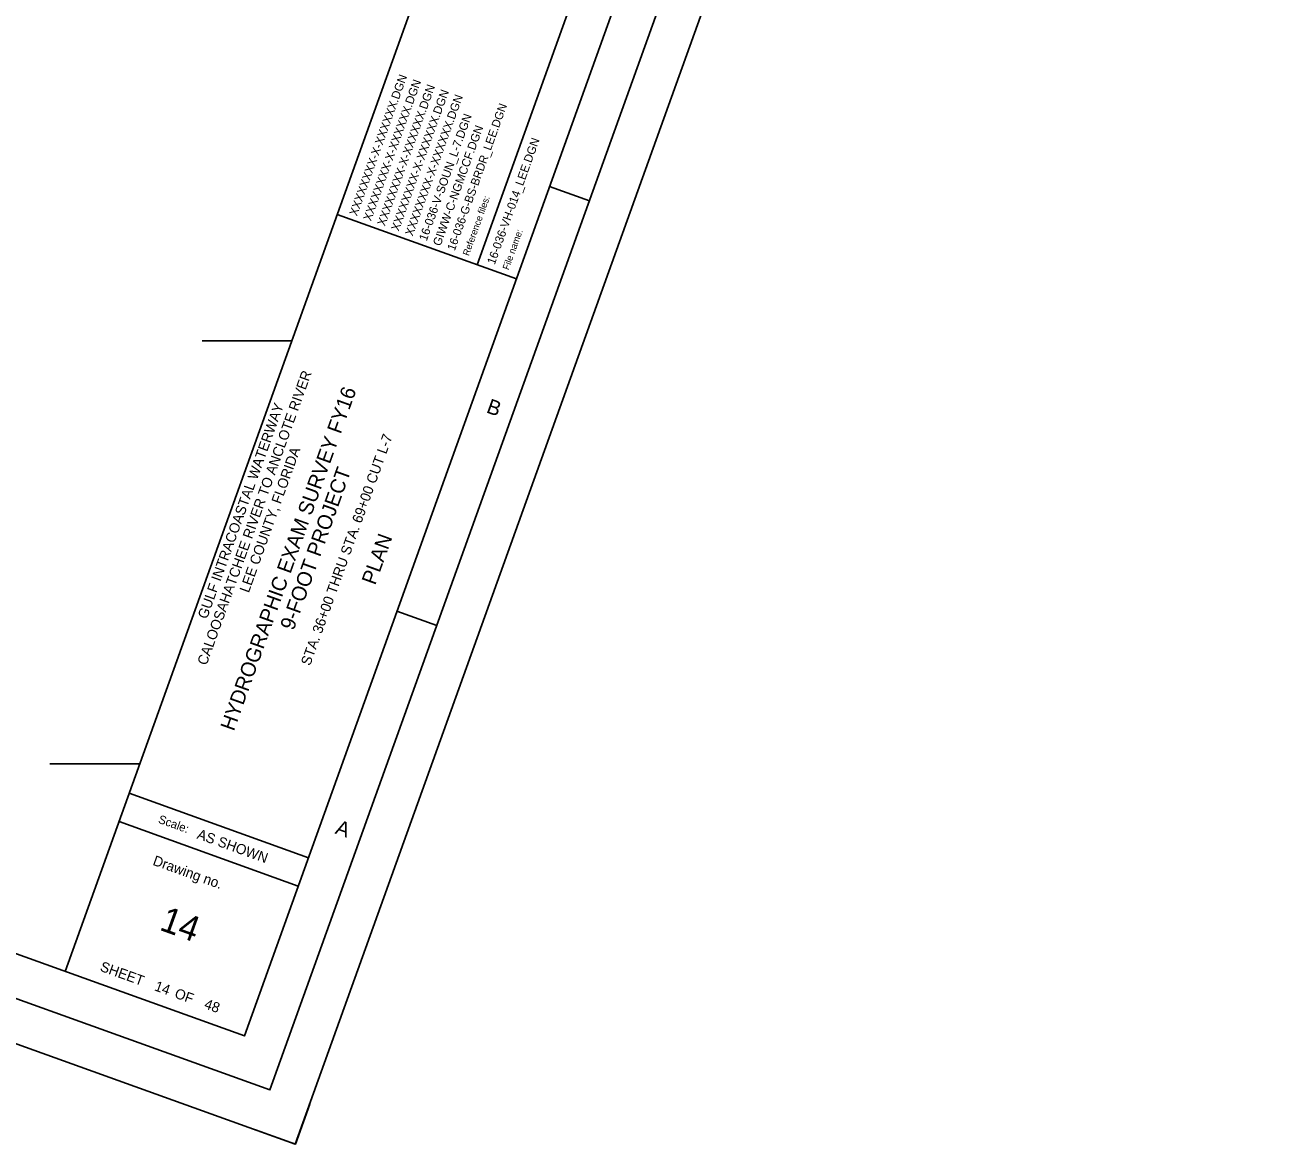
# Model space of a CAD drawing. Extents: x 609104 to 614395, y 782051 to 786739.
# Drawn here: x 612925 to 614395, y 782051 to 783373 of the extents above; entities that cross this region are included whole.
import ezdxf

# ---------------------------------------------------------------- set-up
doc = ezdxf.new("R2010")
doc.units = 0
for name, color, linetype in [('G-ANNO-NPLT', 7, 'Continuous'), ('G-ANNO-TEXT-DRWG', 7, 'Continuous'), ('G-ANNO-TEXT-PROJ', 7, 'Continuous'), ('G-ANNO-TEXT-TTLB', 7, 'Continuous'), ('G-ANNO-TTLB', 7, 'Continuous'), ('V-TOPO-COOR-STAT', 7, 'Continuous')]:
    doc.layers.add(name, color=color, linetype=linetype)

msp = doc.modelspace()

# ---------------------------------------------------------------- linework, layer by layer
at = {"layer": 'G-ANNO-NPLT'}
msp.add_lwpolyline([(610254.1, 786738.7), (614394.6, 785250.1), (613244.3, 782050.6), (609103.8, 783539.2)], close=True, dxfattribs=at)
msp.add_lwpolyline([(613261.4, 782097.6), (613244.5, 782050.6), (613197.4, 782067.5)], dxfattribs=at)
at = {"layer": 'G-ANNO-TTLB'}
for p, q in [((614054.9, 785266), (612972.3, 782254.7)), ((613578.2, 783420.6), (613459.3, 783089.9)), ((613592, 783165.3), (613544.9, 783182.2)), ((613294, 783149.4), (613505.7, 783073.2)), ((613411.5, 782663.5), (613364.5, 782680.4)), ((613048, 782465.2), (613259.8, 782389.1)), ((613035.9, 782431.7), (613247.7, 782355.5))]:
    msp.add_line(p, q, dxfattribs=at)
for points in [[(609167.8, 783569.4), (613214.2, 782114.6), (614330.7, 785220), (610284.3, 786674.7)], [(614266.7, 785189.8), (610385, 786585.4), (609302.3, 783574.1), (613184.1, 782178.5)]]:
    msp.add_lwpolyline(points, close=True, dxfattribs=at)
at = {"layer": 'V-TOPO-COOR-STAT'}
for p, q in [((613134, 783000), (613240.3, 783000)), ((612954.2, 782500), (613060.5, 782500))]:
    msp.add_line(p, q, dxfattribs=at)

# ---------------------------------------------------------------- texts
at = {"layer": 'G-ANNO-TEXT-DRWG'}
for s, height, rotation, p in [('XXXXXXXX-X-XXXXXX.DGN', 10, 70.2251, (613317.2, 783146.7)), ('XXXXXXXX-X-XXXXXX.DGN', 10, 70.2251, (613333.7, 783140.8)), ('XXXXXXXX-X-XXXXXX.DGN', 10, 70.2251, (613350.2, 783134.9)), ('XXXXXXXX-X-XXXXXX.DGN', 10, 70.2251, (613366.6, 783128.9)), ('XXXXXXXX-X-XXXXXX.DGN', 10, 70.2251, (613383.1, 783123)), ('16-036-V-SOUN_L-7.DGN', 10, 70.2251, (613399.6, 783117.1)), ('GIWW-C-NGMCCF.DGN', 10, 70.2251, (613416, 783111.2)), ('16-036-VH-014_LEE.DGN', 10, 70.2251, (613480.1, 783089.3)), ('STA. 36+00 THRU STA. 69+00 CUT L-7 ', 12, 70.2251, (613261.8, 782615.2)), ('PLAN', 17.5, 70.2251, (613338.7, 782710.4)), ('14', 30, 340.2251, (613082.5, 782304.1)), (' 14          48', 12, 340.2251, (613072.7, 782234))]:
    msp.add_text(s, height=height, rotation=rotation, dxfattribs=at).set_placement(p)
at = {"layer": 'G-ANNO-TEXT-PROJ'}
for s, height, p in [('16-036-G-BS-BRDR_LEE.DGN', 9.8, (613432.8, 783105.6)), ('CALOOSAHATCHEE RIVER TO ANCLOTE RIVER', 12, (613139.3, 782615.6)), ('HYDROGRAPHIC EXAM SURVEY FY16', 17.5, (613171.6, 782537.8)), ('GULF INTRACOASTAL WATERWAY', 12, (613139.8, 782670.3)), ('LEE COUNTY, FLORIDA', 12, (613189.3, 782701.4)), ('9-FOOT PROJECT', 17.5, (613242.3, 782656.8))]:
    msp.add_text(s, height=height, rotation=70.2251, dxfattribs=at).set_placement(p)
at = {"layer": 'G-ANNO-TEXT-TTLB'}
for s, height, rotation, p in [('Reference files:', 8, 70.2251, (613449.5, 783099.7)), ('File name:', 8, 70.2251, (613496.6, 783083)), ('Scale:', 10, 340.2251, (613081.4, 782430.5)), ('AS SHOWN', 12, 340.2251, (613127.1, 782412)), ('Drawing no.', 12, 340.2251, (613074.9, 782380.8)), ('SHEET         OF', 12, 340.2251, (613012.5, 782255.6))]:
    msp.add_text(s, height=height, rotation=rotation, dxfattribs=at).set_placement(p)
at = {"layer": 'G-ANNO-TTLB'}
for s, p in [('B', (613469.2, 782915.5)), ('A', (613290.4, 782417.9))]:
    msp.add_text(s, height=17.5, rotation=340.2251, dxfattribs=at).set_placement(p)

doc.saveas('drawing.dxf')
